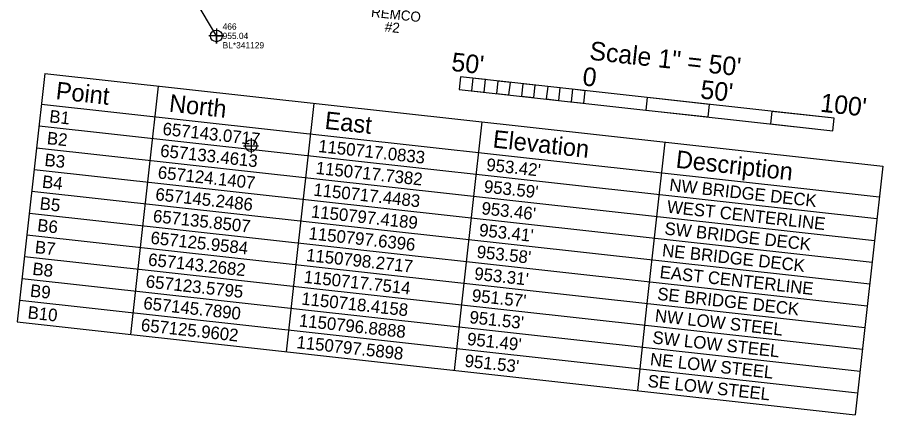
# Model space of a CAD drawing. Extents: x 1150279 to 1151282, y 655434 to 657999.
# Drawn here: x 1150700.1 to 1151045.5, y 656828.1 to 656986.7 of the extents above; entities that cross this region are included whole.
import ezdxf

# ---------------------------------------------------------------- set-up
doc = ezdxf.new("R2010")
doc.units = 0
for name, color, linetype in [('Cogo Default Point CELL', 7, 'Continuous'), ('CTL Sheet Datum Description CELL', 7, 'Continuous'), ('Exist Other Culture Gate', 7, 'Continuous'), ('Exist Other Culture Gate Cogo Comment', 7, 'Continuous'), ('Exist Other Culture Gate Cogo Elevation', 7, 'Continuous'), ('Exist Other Culture Gate Cogo Number', 7, 'Continuous'), ('Exist Other Culture Gate Cogo Point CELL', 7, 'Continuous'), ('Exist Other Culture Located Object Text', 7, 'Continuous'), ('Exist Utilities Power Joint Use Telephone Text', 7, 'Continuous')]:
    doc.layers.add(name, color=color, linetype=linetype)

msp = doc.modelspace()

# ---------------------------------------------------------------- linework, layer by layer
at = {"layer": 'Cogo Default Point CELL'}
for points in [[(1150793.42, 656938.45), (1150793.42, 656935.45)], [(1150790.42, 656935.45), (1150793.42, 656935.45)], [(1150793.42, 656935.45), (1150796.42, 656935.45)], [(1150793.42, 656935.45), (1150793.42, 656932.45)]]:
    msp.add_lwpolyline(points, dxfattribs=at)
msp.add_circle((1150793.42, 656935.45), 2.34, dxfattribs=at)
at = {"layer": 'CTL Sheet Datum Description CELL'}
for points in [[(1150876.48, 656957.93), (1151025.57, 656941.43), (1151026.12, 656946.4), (1150877.03, 656962.9)], [(1150881.45, 656957.38), (1150886.42, 656956.83), (1150886.97, 656961.8), (1150882, 656962.35)], [(1150891.39, 656956.28), (1150896.36, 656955.73), (1150896.91, 656960.7), (1150891.94, 656961.25)], [(1150901.33, 656955.18), (1150906.3, 656954.63), (1150906.85, 656959.6), (1150901.88, 656960.15)], [(1150911.27, 656954.08), (1150916.24, 656953.53), (1150916.79, 656958.5), (1150911.82, 656959.05)], [(1150921.21, 656952.98), (1150926.18, 656952.43), (1150926.72, 656957.4), (1150921.76, 656957.95)], [(1150951.02, 656949.68), (1150975.87, 656946.93), (1150976.42, 656951.9), (1150951.57, 656954.65)], [(1151000.72, 656944.18), (1151025.57, 656941.43), (1151026.12, 656946.4), (1151001.27, 656949.15)]]:
    msp.add_lwpolyline(points, close=True, dxfattribs=at)
at = {"layer": 'Exist Other Culture Gate'}
msp.add_line((1150779.56, 656979.27), (1150771.14, 656993.52), dxfattribs=at)
at = {"layer": 'Exist Other Culture Gate Cogo Point CELL'}
msp.add_lwpolyline([(1150779.56, 656982.27), (1150779.56, 656976.27), (1150779.56, 656979.27), (1150782.56, 656979.27), (1150776.56, 656979.27)], dxfattribs=at)
msp.add_circle((1150779.56, 656979.27), 2.34, dxfattribs=at)
at = {"layer": 'Exist Other Culture Located Object Text'}
for p, q in [((1150711.08, 656964.22), (1150703.96, 656899.86)), ((1150711.08, 656964.22), (1151045.54, 656927.21)), ((1150756.3, 656959.21), (1150749.18, 656894.86)), ((1150709.73, 656952.04), (1151044.19, 656915.04)), ((1150818.42, 656952.34), (1150811.3, 656887.98)), ((1150708.77, 656943.34), (1151043.23, 656906.34)), ((1150708.77, 656943.34), (1151043.23, 656906.34)), ((1150708.77, 656943.34), (1151043.23, 656906.34)), ((1150708.77, 656943.34), (1151043.23, 656906.34)), ((1150708.77, 656943.34), (1151043.23, 656906.34)), ((1150885.51, 656944.92), (1150878.39, 656880.56)), ((1150958.57, 656936.83), (1150951.45, 656872.48)), ((1150707.8, 656934.65), (1151042.26, 656897.64)), ((1150707.8, 656934.65), (1151042.26, 656897.64)), ((1150707.8, 656934.65), (1151042.26, 656897.64)), ((1150707.8, 656934.65), (1151042.26, 656897.64)), ((1150707.8, 656934.65), (1151042.26, 656897.64)), ((1150706.84, 656925.95), (1151041.3, 656888.95)), ((1150706.84, 656925.95), (1151041.3, 656888.95)), ((1150706.84, 656925.95), (1151041.3, 656888.95)), ((1150706.84, 656925.95), (1151041.3, 656888.95)), ((1150706.84, 656925.95), (1151041.3, 656888.95)), ((1151045.54, 656927.21), (1151038.42, 656862.86)), ((1150705.88, 656917.25), (1151040.34, 656880.25)), ((1150705.88, 656917.25), (1151040.34, 656880.25)), ((1150705.88, 656917.25), (1151040.34, 656880.25)), ((1150705.88, 656917.25), (1151040.34, 656880.25)), ((1150705.88, 656917.25), (1151040.34, 656880.25)), ((1150704.92, 656908.56), (1151039.38, 656871.55)), ((1150704.92, 656908.56), (1151039.38, 656871.55)), ((1150704.92, 656908.56), (1151039.38, 656871.55)), ((1150704.92, 656908.56), (1151039.38, 656871.55)), ((1150704.92, 656908.56), (1151039.38, 656871.55)), ((1150703.96, 656899.86), (1150700.11, 656865.07)), ((1150703.96, 656899.86), (1151038.42, 656862.86)), ((1150703.96, 656899.86), (1151038.42, 656862.86)), ((1150703.96, 656899.86), (1151038.42, 656862.86)), ((1150703.96, 656899.86), (1151038.42, 656862.86)), ((1150703.96, 656899.86), (1151038.42, 656862.86)), ((1150749.18, 656894.86), (1150745.33, 656860.07)), ((1150702.99, 656891.16), (1151037.45, 656854.16)), ((1150702.99, 656891.16), (1151037.45, 656854.16)), ((1150702.99, 656891.16), (1151037.45, 656854.16)), ((1150702.99, 656891.16), (1151037.45, 656854.16)), ((1150702.99, 656891.16), (1151037.45, 656854.16)), ((1150811.3, 656887.98), (1150807.45, 656853.19)), ((1150702.03, 656882.46), (1151036.49, 656845.46)), ((1150702.03, 656882.46), (1151036.49, 656845.46)), ((1150702.03, 656882.46), (1151036.49, 656845.46)), ((1150702.03, 656882.46), (1151036.49, 656845.46)), ((1150702.03, 656882.46), (1151036.49, 656845.46)), ((1150878.39, 656880.56), (1150874.54, 656845.77)), ((1150701.07, 656873.77), (1151035.53, 656836.76)), ((1150701.07, 656873.77), (1151035.53, 656836.76)), ((1150701.07, 656873.77), (1151035.53, 656836.76)), ((1150701.07, 656873.77), (1151035.53, 656836.76)), ((1150701.07, 656873.77), (1151035.53, 656836.76)), ((1150951.45, 656872.48), (1150947.6, 656837.69)), ((1150700.11, 656865.07), (1151034.57, 656828.07)), ((1150700.11, 656865.07), (1151034.57, 656828.07)), ((1150700.11, 656865.07), (1151034.57, 656828.07)), ((1150700.11, 656865.07), (1151034.57, 656828.07)), ((1150700.11, 656865.07), (1151034.57, 656828.07)), ((1151038.42, 656862.86), (1151034.57, 656828.07))]:
    msp.add_line(p, q, dxfattribs=at)

# ---------------------------------------------------------------- texts
at = {"layer": 'CTL Sheet Datum Description CELL'}
for s, p in [('Scale 1" = 50\'', (1150928.22, 656969.81)), ("50'", (1150873.12, 656965.34)), ('0', (1150925.44, 656959.55)), ("50'", (1150972.51, 656954.34)), ("100'", (1151020.36, 656949.05))]:
    msp.add_text(s, height=7.4, rotation=353.6867, dxfattribs=at).set_placement(p)
at = {"layer": 'Exist Other Culture Gate Cogo Comment'}
msp.add_text('BL*341129', height=2.5, dxfattribs=at).set_placement((1150782.06, 656974.27))
at = {"layer": 'Exist Other Culture Gate Cogo Elevation'}
msp.add_text('955.04', height=2.5, dxfattribs=at).set_placement((1150782.06, 656978.02))
at = {"layer": 'Exist Other Culture Gate Cogo Number'}
msp.add_text('466', height=2.5, dxfattribs=at).set_placement((1150782.06, 656981.77))
at = {"layer": 'Exist Other Culture Located Object Text'}
for s, height, p in [('Point', 7, (1150715.24, 656954.07)), ('North', 7, (1150760.46, 656949.07)), ('B1', 5, (1150712.7, 656944.79)), ('East', 7, (1150822.58, 656942.2)), ('657143.0717', 5, (1150757.92, 656939.79)), ('B2', 5, (1150711.74, 656936.1)), ('Elevation', 7, (1150889.67, 656934.77)), ('657133.4613', 5, (1150756.96, 656931.09)), ('1150717.0833', 5, (1150820.05, 656932.92)), ('B3', 5, (1150710.78, 656927.4)), ('Description', 7, (1150962.73, 656926.69)), ('1150717.7382', 5, (1150819.08, 656924.22)), ("953.42'", 5, (1150887.14, 656925.5)), ('657124.1407', 5, (1150756, 656922.4)), ('B4', 5, (1150709.81, 656918.7)), ("953.59'", 5, (1150886.17, 656916.8)), ('NW BRIDGE DECK', 5, (1150960.19, 656917.41)), ('657145.2486', 5, (1150755.04, 656913.7)), ('1150717.4483', 5, (1150818.12, 656915.52)), ('B5', 5, (1150708.85, 656910.01)), ('1150797.4189', 5, (1150817.16, 656906.83)), ("953.46'", 5, (1150885.21, 656908.1)), ('WEST CENTERLINE', 5, (1150959.23, 656908.72)), ('657135.8507', 5, (1150754.08, 656905)), ('B6', 5, (1150707.89, 656901.31)), ('SW BRIDGE DECK', 5, (1150958.27, 656900.02)), ('657125.9584', 5, (1150753.11, 656896.31)), ('1150797.6396', 5, (1150816.2, 656898.13)), ("953.41'", 5, (1150884.25, 656899.41)), ('B7', 5, (1150706.93, 656892.61)), ('1150798.2717', 5, (1150815.23, 656889.43)), ("953.58'", 5, (1150883.29, 656890.71)), ('NE BRIDGE DECK', 5, (1150957.3, 656891.32)), ('657143.2682', 5, (1150752.15, 656887.61)), ('B8', 5, (1150705.96, 656883.92)), ('EAST CENTERLINE', 5, (1150956.34, 656882.63)), ('657123.5795', 5, (1150751.19, 656878.91)), ('1150717.7514', 5, (1150814.27, 656880.74)), ("953.31'", 5, (1150882.33, 656882.01)), ('B9', 5, (1150705, 656875.22)), ('1150718.4158', 5, (1150813.31, 656872.04)), ("951.57'", 5, (1150881.36, 656873.31)), ('SE BRIDGE DECK', 5, (1150955.38, 656873.93)), ('657145.7890', 5, (1150750.23, 656870.22)), ('B10', 5, (1150704.04, 656866.52)), ('NW LOW STEEL', 5, (1150954.42, 656865.23)), ('1150796.8888', 5, (1150812.35, 656863.34)), ("951.53'", 5, (1150880.4, 656864.62)), ('657125.9602', 5, (1150749.26, 656861.52)), ("951.49'", 5, (1150879.44, 656855.92)), ('SW LOW STEEL', 5, (1150953.45, 656856.53)), ('1150797.5898', 5, (1150811.39, 656854.65)), ('NE LOW STEEL', 5, (1150952.49, 656847.84)), ("951.53'", 5, (1150878.48, 656847.22)), ('SE LOW STEEL', 5, (1150951.53, 656839.14))]:
    msp.add_text(s, height=height, rotation=353.6867, dxfattribs=at).set_placement(p)
at = {"layer": 'Exist Utilities Power Joint Use Telephone Text'}
for s, p in [('REMCO', (1150841.17, 656986.94)), ('#2', (1150846.63, 656981.05))]:
    msp.add_text(s, height=4, rotation=353.6867, dxfattribs=at).set_placement(p)

doc.saveas('drawing.dxf')
